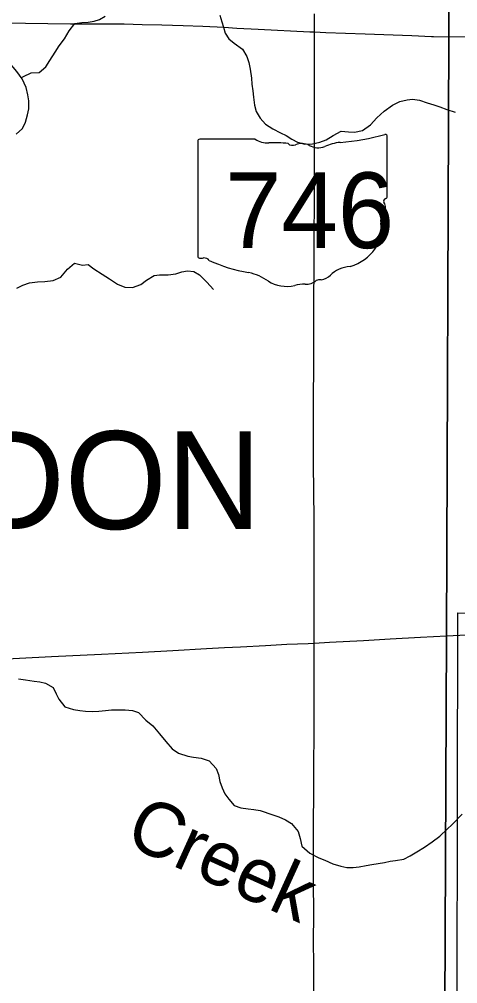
# Model space of a CAD drawing. Extents: x 0 to 45.9, y 0 to 22.
# Drawn here: x 4.718 to 5.48, y 15.053 to 16.732 of the extents above; entities that cross this region are included whole.
import ezdxf

# ---------------------------------------------------------------- set-up
doc = ezdxf.new("R2010")
doc.units = 0
for name, color, linetype in [('Default', 7, 'Continuous'), ('GM_X_Major_River', 7, 'Continuous'), ('GM_X_Minor_River', 7, 'Continuous'), ('GM_X_Minor_River_Text', 7, 'Continuous'), ('GM_X_Section', 7, 'Continuous'), ('GM_X_State_Location', 7, 'Continuous'), ('GM_X_State_Route', 7, 'Continuous'), ('GM_X_State_Shield', 7, 'Continuous'), ('GM_X_Township_Road', 7, 'Continuous'), ('GM_X_Township_Text', 7, 'Continuous'), ('SH_Text', 7, 'Continuous')]:
    doc.layers.add(name, color=color, linetype=linetype)

msp = doc.modelspace()

# ---------------------------------------------------------------- linework, layer by layer
at = {"layer": 'Default'}
msp.add_lwpolyline([(2.1, 19.7114), (2.1, 14.1), (5.4538, 14.1), (5.4606, 15.6588), (5.4651, 16.7018), (5.4694, 17.7061), (5.4802, 18.3214), (5.4737, 18.7216), (5.4752, 19.0482), (5.4759, 19.2109), (5.4773, 19.7108), (5.0826, 19.712), (3.7367, 19.7072), (2.15, 19.7113)], close=True, dxfattribs=at)
msp.add_lwpolyline([(5.4773, 19.7108), (5.4759, 19.2109), (5.4752, 19.0482), (5.4737, 18.7216), (5.4802, 18.3214), (5.4694, 17.7061), (5.4651, 16.7018), (5.4606, 15.6588), (5.4538, 14.1)], dxfattribs=at)
at = {"layer": 'GM_X_Major_River'}
for points in [[(4.7299, 16.6133), (4.7225, 16.6282), (4.7136, 16.6412), (4.7005, 16.6562), (4.6942, 16.6665), (4.6894, 16.6803), (4.6873, 16.6913), (4.686, 16.7057), (4.6862, 16.719), (4.6852, 16.7357)], [(4.7121, 16.532), (4.7232, 16.5421), (4.7283, 16.553), (4.7323, 16.5655), (4.7343, 16.5761), (4.7341, 16.5901), (4.7327, 16.6004), (4.7299, 16.6133)]]:
    msp.add_lwpolyline(points, dxfattribs=at)
at = {"layer": 'GM_X_Minor_River'}
for points in [[(4.721, 16.6304), (4.7248, 16.6327), (4.7382, 16.639), (4.7522, 16.6396), (4.7641, 16.6493), (4.7711, 16.6606), (4.78, 16.6749), (4.7874, 16.6858), (4.7963, 16.6982), (4.8048, 16.7121), (4.8145, 16.7249), (4.8266, 16.7266), (4.8373, 16.7272), (4.8479, 16.7286), (4.8575, 16.7319), (4.8674, 16.7378)], [(5.0666, 16.7393), (5.0703, 16.7279), (5.0732, 16.7183), (5.0761, 16.7081), (5.082, 16.6981), (5.0918, 16.6904), (5.106, 16.6803), (5.1138, 16.6673), (5.1171, 16.6567), (5.1196, 16.6452), (5.1217, 16.6293), (5.1223, 16.6194), (5.1237, 16.6076), (5.125, 16.5962), (5.1271, 16.5826), (5.13, 16.5715), (5.137, 16.56), (5.146, 16.5497), (5.1588, 16.5412), (5.172, 16.5341), (5.1818, 16.5295), (5.1916, 16.5233), (5.2014, 16.5182), (5.2146, 16.5146), (5.2279, 16.5152), (5.2408, 16.518), (5.2515, 16.5224), (5.2637, 16.5295), (5.2775, 16.5373), (5.2904, 16.5363), (5.301, 16.5358), (5.3147, 16.5387), (5.3285, 16.5483), (5.3397, 16.5603), (5.3527, 16.5723), (5.3669, 16.5827), (5.3799, 16.589), (5.3925, 16.5919), (5.402, 16.5929), (5.4137, 16.5912), (5.4273, 16.5865), (5.439, 16.5829), (5.4492, 16.5794), (5.4613, 16.575), (5.4762, 16.5704)], [(4.7137, 16.2638), (4.7241, 16.2693), (4.7355, 16.2729), (4.7496, 16.2747), (4.7621, 16.2752), (4.7765, 16.2773), (4.7899, 16.2832), (4.8018, 16.2967), (4.8137, 16.3076), (4.8277, 16.304), (4.8376, 16.305), (4.8474, 16.2976), (4.8617, 16.2883), (4.8748, 16.2802), (4.8884, 16.2709), (4.9012, 16.2654), (4.9149, 16.2648), (4.929, 16.27), (4.9389, 16.2778), (4.9523, 16.286), (4.9618, 16.2873), (4.9766, 16.2868), (4.9899, 16.2889), (5.0002, 16.2921), (5.0101, 16.2939), (5.0211, 16.2926), (5.0313, 16.2868), (5.044, 16.2741), (5.0556, 16.2614)], [(4.7163, 15.5835), (4.7284, 15.5818), (4.7435, 15.5793), (4.7534, 15.5784), (4.7632, 15.576), (4.7768, 15.5686), (4.7819, 15.5576), (4.7864, 15.548), (4.7968, 15.5346), (4.8123, 15.5299), (4.8233, 15.5282), (4.8328, 15.5273), (4.8445, 15.5264), (4.8563, 15.5274), (4.8677, 15.5283), (4.8779, 15.5293), (4.8889, 15.5296)], [(4.8889, 15.5296), (4.9019, 15.5298), (4.9144, 15.5285), (4.9249, 15.5249), (4.938, 15.5118), (4.95, 15.5014), (4.9616, 15.4876), (4.9724, 15.4742), (4.9836, 15.4615), (4.9945, 15.4538), (5.0108, 15.4486), (5.021, 15.447), (5.0343, 15.4453), (5.0479, 15.4409), (5.0602, 15.4275), (5.0642, 15.4172), (5.0664, 15.405), (5.0704, 15.3936), (5.0755, 15.3833), (5.0822, 15.3737), (5.0916, 15.363), (5.1033, 15.3586), (5.1158, 15.3569), (5.1256, 15.356), (5.137, 15.354), (5.1585, 15.3465), (5.1691, 15.3429), (5.1808, 15.3379), (5.191, 15.3316), (5.2029, 15.3178), (5.2062, 15.3056), (5.2094, 15.2923), (5.2229, 15.28), (5.2387, 15.2718), (5.2493, 15.2675), (5.2629, 15.2616), (5.2772, 15.2573), (5.2874, 15.2552), (5.2984, 15.2551), (5.3091, 15.2561), (5.3213, 15.2582), (5.3308, 15.26), (5.3418, 15.2617), (5.3528, 15.2638), (5.3627, 15.266), (5.3722, 15.267), (5.3867, 15.2694), (5.3974, 15.275), (5.4092, 15.282), (5.4226, 15.2906), (5.436, 15.2995), (5.4491, 15.3096), (5.4625, 15.3223), (5.47, 15.3291)], [(5.47, 15.3291), (5.4883, 15.3481)]]:
    msp.add_lwpolyline(points, dxfattribs=at)
at = {"layer": 'GM_X_Section'}
msp.add_lwpolyline([(6.5014, 15.6897), (6.4893, 14.6816), (5.4789, 14.694), (5.4804, 15.6984)], close=True, dxfattribs=at)
at = {"layer": 'GM_X_State_Route'}
for points in [[(5.2308, 15.6458), (5.2308, 15.6559), (5.2309, 15.669), (5.2309, 15.697), (5.2309, 15.7561), (5.2306, 15.8245), (5.2305, 15.8618), (5.2297, 15.9581), (5.2296, 16.0048), (5.2297, 16.0825), (5.2301, 16.1167), (5.23, 16.1447), (5.2303, 16.2006), (5.2303, 16.2473), (5.2306, 16.2939), (5.2307, 16.3436), (5.231, 16.4245), (5.231, 16.5022), (5.2312, 16.555), (5.2313, 16.5892), (5.2311, 16.6234), (5.2312, 16.6918), (5.2313, 16.7102), (5.2315, 16.7416)], [(4.6404, 15.6157), (4.718, 15.6193), (4.7738, 15.6222), (4.8606, 15.6267), (4.932, 15.6302), (4.9847, 15.6329), (5.0436, 15.6362), (5.0746, 15.6378), (5.1025, 15.6395), (5.146, 15.6416), (5.1832, 15.6436), (5.2204, 15.6453), (5.2308, 15.6458), (5.2576, 15.6474), (5.3165, 15.6503), (5.363, 15.6532), (5.4158, 15.6559), (5.4608, 15.6583)], [(5.4608, 15.6583), (5.4954, 15.6601)], [(5.2292, 14.9634), (5.2301, 15.0566), (5.23, 15.0939), (5.2298, 15.1187), (5.2299, 15.1809), (5.2296, 15.2244), (5.2297, 15.2554), (5.2296, 15.2865), (5.2298, 15.3455), (5.23, 15.3704), (5.2302, 15.3984), (5.2303, 15.4356), (5.2304, 15.4853), (5.2305, 15.5226), (5.2306, 15.5817), (5.2309, 15.6139), (5.2308, 15.6343), (5.2308, 15.6458)]]:
    msp.add_lwpolyline(points, dxfattribs=at)
at = {"layer": 'GM_X_State_Shield'}
for p, q in [((5.3579, 16.4234), (5.3579, 16.528)), ((5.0283, 16.5196), (5.0283, 16.3195)), ((5.1281, 16.5231), (5.0316, 16.5231)), ((5.3579, 16.4234), (5.3579, 16.4234))]:
    msp.add_line(p, q, dxfattribs=at)
for centre, major_axis, start_param, end_param in [((5.2405, 16.7959), (0.3495, 0), 4.814394, 5.042369), ((5.3542, 16.5285), (0.00367, 0), 6.141152, 7.989035), ((5.0321, 16.5201), (0.00382, 0), 1.712693, 3.28349), ((5.1511, 16.5463), (0.037, 0), 4.042523, 4.731795), ((5.1633, 16.4107), (0.133, 0), 1.404758, 1.657858), ((5.1935, 16.5211), (0.0107, 0), 3.836095, 5.185415), ((5.2092, 16.498), (0.0222, 0), 0.950623, 2.079405), ((5.2379, 16.5297), (0.0267, 0), 4.081561, 5.145723), ((5.2851, 16.462), (0.0703, 0), 1.699011, 2.107814), ((5.357, 16.4157), (0.00568, 0), 1.883978, 3.671073), ((5.3209, 16.4024), (0.0341, 0), 5.934695, 6.695948), ((5.354, 16.4229), (0.00393, 0), 5.05454, 6.418171), ((5.371, 16.3795), (0.0248, 0), 2.387724, 3.262537), ((5.2601, 16.3662), (0.0874, 0), 5.101752, 6.440018), ((5.0321, 16.3191), (0.00385, 0), 3.00124, 4.508301), ((5.0327, 16.3396), (0.0294, 0), 4.665946, 4.897461), ((5.0387, 16.308), (0.0106, 0), 0.519207, 1.627899), ((5.1725, 16.4878), (0.2524, 0), 4.195997, 4.488961), ((5.2969, 16.2633), (0.0479, 0), 1.647645, 2.488434), ((5.0973, 16.2296), (0.079, 0), 0.823519, 1.323587), ((5.1827, 16.307), (0.0501, 0), 4.026481, 4.996735), ((5.2153, 16.292), (0.0267, 0), 4.691044, 5.507374), ((5.2395, 16.2726), (0.00752, 0), 1.147584, 2.315152), ((5.2363, 16.3001), (0.0282, 0), 4.937069, 5.64225), ((5.2117, 16.2378), (0.0412, 0), 1.495662, 1.94098)]:
    msp.add_ellipse(centre, major_axis=major_axis, ratio=0.8, start_param=start_param, end_param=end_param, dxfattribs=at)
at = {"layer": 'GM_X_Township_Road'}
for points in [[(4.4133, 16.7278), (4.431, 16.728), (4.459, 16.7284), (4.487, 16.7285), (4.5211, 16.7279), (4.5926, 16.7269), (4.633, 16.7265), (4.689, 16.726), (4.8071, 16.7244), (4.8475, 16.7243), (4.8755, 16.7243), (4.9003, 16.7241), (4.9314, 16.7233), (4.9656, 16.7224), (5.0029, 16.7213), (5.037, 16.72), (5.0743, 16.7181), (5.096, 16.7169), (5.1332, 16.7151), (5.2233, 16.7105), (5.2313, 16.7102)], [(5.2313, 16.7102), (5.2512, 16.7093), (5.3195, 16.7069), (5.4003, 16.7037), (5.4345, 16.7024), (5.4382, 16.7023), (5.4653, 16.7013)], [(5.4653, 16.7013), (5.5685, 16.7021), (5.6369, 16.7037), (5.7332, 16.7058), (5.7436, 16.7061)]]:
    msp.add_lwpolyline(points, dxfattribs=at)
at = {"layer": 'SH_Text'}
for points in [[(5.4538, 14.1), (5.4606, 15.6588), (5.4651, 16.7018), (5.4694, 17.7061), (5.4802, 18.3214), (5.4737, 18.7216), (5.4752, 19.0482), (5.4759, 19.2109), (5.4773, 19.7108)], [(5.4773, 19.7108), (5.4759, 19.2109), (5.4752, 19.0482), (5.4737, 18.7216), (5.4802, 18.3214), (5.4694, 17.7061), (5.4651, 16.7018), (5.4606, 15.6588), (5.4538, 14.1)]]:
    msp.add_lwpolyline(points, dxfattribs=at)

# ---------------------------------------------------------------- texts
at = {"layer": 'GM_X_Minor_River_Text'}
msp.add_text('Creek', height=0.09472, rotation=335.6132, dxfattribs=at).set_placement((4.8981, 15.2971))
at = {"layer": 'GM_X_State_Location'}
msp.add_text('746', height=0.000189, rotation=0, dxfattribs=at).set_placement((5.1225, 16.3925))
for s in ['s', 'r']:
    msp.add_text(s, height=0.000189, dxfattribs=at).set_placement((5.1894, 16.4063))
at = {"layer": 'GM_X_State_Shield'}
msp.add_text('746', height=0.13184, dxfattribs=at).set_placement((5.0757, 16.3336))
at = {"layer": 'GM_X_Township_Text'}
msp.add_text('CLARIDON', height=0.17045, rotation=0, dxfattribs=at).set_placement((3.961, 15.8443))

doc.saveas('drawing.dxf')
